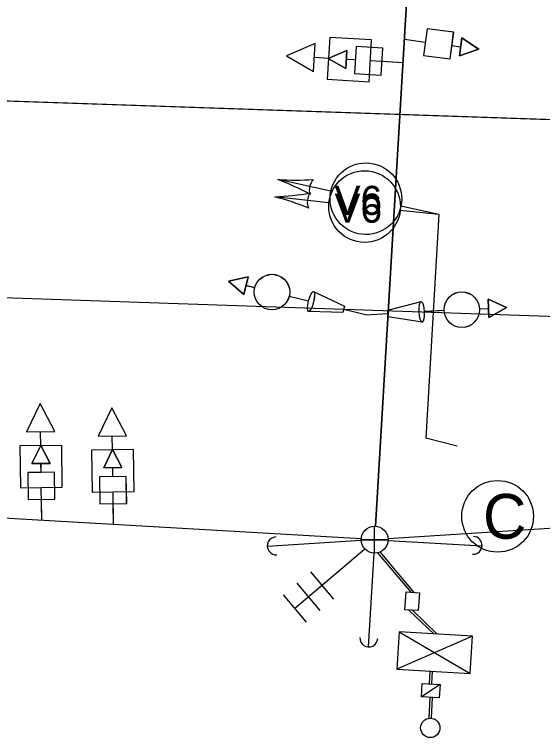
# Model space of a CAD drawing. Extents: x 647787 to 668496, y 640478 to 654412.
# Drawn here: x 661688.8 to 661747.7, y 647230.2 to 647310.9 of the extents above; entities that cross this region are included whole.
import ezdxf

# ---------------------------------------------------------------- set-up
doc = ezdxf.new("R2010")
doc.units = 0
for name, color, linetype in [('Default', 7, 'Continuous'), ('TEMP_SIGNAL POLES', 7, 'Continuous'), ('TEMP_SIGNAL_CONDUIT', 7, 'Continuous'), ('TEMP_SIGNAL_CONTROLLER', 7, 'Continuous'), ('TEMP_SIGNAL_HEAD_STAGE 2', 7, 'Continuous'), ('TEMP_SIGNAL_HEAD_STAGE 2 SHILO', 7, 'Continuous'), ('TEMP_SIGNAL_HEAD_Stage 3', 7, 'Continuous'), ('TEMP_SIGNAL_HEAD_STAGE 4 SHILO_OLD', 7, 'Continuous'), ('TEMP_SIGNAL_HEAD_STAGE4', 7, 'Continuous'), ('TEMP_SIGNAL_POLE_STAGE 2-3', 7, 'Continuous'), ('TEMP_SIGNAL_POLES_STAGE 2', 7, 'Continuous'), ('TEMP_SIGNAL_POLES_STAGES 3-4', 7, 'Continuous'), ('TEMP_SIGNAL_PULL BOX', 7, 'Continuous'), ('TEXT_TEMP_SIGNAL_POLES_STAGE 2', 7, 'Continuous'), ('TEXT_TEMP_SIGNAL_POLES_STAGE 3', 7, 'Continuous'), ('TEXT_TEMP_SIGNAL_POLES_STAGE 4', 7, 'Continuous')]:
    doc.layers.add(name, color=color, linetype=linetype)

msp = doc.modelspace()

# ---------------------------------------------------------------- linework, layer by layer
at = {"layer": 'Default'}
for points in [[(662136.439, 647331.769), (661882.019, 647294.613), (661114.402, 647320.889)], [(662108.288, 647310.771), (661853.868, 647273.614), (661086.251, 647299.89)], [(661761.55, 647298.737), (661606.212, 647304.054)], [(661761.55, 647298.737), (661606.212, 647304.054)]]:
    msp.add_lwpolyline(points, dxfattribs=at)
at = {"layer": 'TEMP_SIGNAL POLES'}
for p, q in [((661728.991, 647250.813), (661728.991, 647253.813)), ((661728.991, 647250.813), (661728.991, 647253.813)), ((661728.991, 647250.813), (661728.991, 647253.813)), ((661728.993, 647250.815), (661728.993, 647253.815)), ((661727.491, 647252.313), (661730.491, 647252.313)), ((661727.491, 647252.313), (661730.491, 647252.313)), ((661727.491, 647252.313), (661730.491, 647252.313)), ((661727.493, 647252.315), (661730.493, 647252.315)), ((661721.821, 647248.739), (661724.408, 647245.689)), ((661721.821, 647248.739), (661724.408, 647245.689)), ((661721.821, 647248.739), (661724.408, 647245.689)), ((661721.824, 647248.741), (661724.411, 647245.69)), ((661720.296, 647247.446), (661722.883, 647244.395)), ((661720.296, 647247.446), (661722.883, 647244.395)), ((661720.296, 647247.446), (661722.883, 647244.395)), ((661720.298, 647247.448), (661722.885, 647244.397)), ((661718.77, 647246.153), (661721.357, 647243.102)), ((661718.77, 647246.153), (661721.357, 647243.102)), ((661718.77, 647246.153), (661721.357, 647243.102)), ((661718.773, 647246.154), (661721.36, 647243.103))]:
    msp.add_line(p, q, dxfattribs=at)
for points in [[(661720.064, 647244.627), (661727.906, 647251.277)], [(661720.064, 647244.627), (661727.906, 647251.277)], [(661720.064, 647244.627), (661727.906, 647251.277)], [(661720.066, 647244.629), (661727.909, 647251.279)]]:
    msp.add_lwpolyline(points, dxfattribs=at)
for centre in [(661728.991, 647252.313), (661728.991, 647252.313), (661728.991, 647252.313), (661728.993, 647252.315)]:
    msp.add_circle(centre, 1.5, dxfattribs=at)
at = {"layer": 'TEMP_SIGNAL_CONDUIT'}
for p, q in [((661733.402, 647246.426), (661729.611, 647250.947)), ((661733.402, 647246.426), (661729.611, 647250.947)), ((661733.057, 647246.448), (661729.359, 647250.859)), ((661733.057, 647246.448), (661729.359, 647250.859)), ((661735.579, 647241.795), (661732.816, 647244.459)), ((661735.579, 647241.795), (661732.816, 647244.459)), ((661735.963, 647241.772), (661733.201, 647244.436)), ((661735.963, 647241.772), (661733.201, 647244.436)), ((661735.119, 647236.217), (661735.196, 647237.651)), ((661735.119, 647236.217), (661735.196, 647237.651)), ((661735.369, 647236.206), (661735.446, 647237.636)), ((661735.369, 647236.206), (661735.446, 647237.636)), ((661736.294, 647236.149), (661734.21, 647234.767)), ((661736.294, 647236.149), (661734.21, 647234.767)), ((661735.071, 647232.382), (661735.196, 647234.703)), ((661735.071, 647232.382), (661735.196, 647234.703)), ((661735.322, 647232.383), (661735.446, 647234.688)), ((661735.322, 647232.383), (661735.446, 647234.688))]:
    msp.add_line(p, q, dxfattribs=at)
msp.add_lwpolyline([(661734.297, 647236.265), (661736.294, 647236.149), (661736.207, 647234.652), (661734.21, 647234.767)], close=True, dxfattribs=at)
msp.add_lwpolyline([(661734.297, 647236.265), (661736.294, 647236.149), (661736.207, 647234.652), (661734.21, 647234.767)], close=True, dxfattribs=at)
at = {"layer": 'TEMP_SIGNAL_CONTROLLER'}
for p, q in [((661739.919, 647241.533), (661731.465, 647237.876)), ((661739.919, 647241.533), (661731.465, 647237.876)), ((661731.715, 647242.028), (661739.668, 647237.381)), ((661731.715, 647242.028), (661739.668, 647237.381))]:
    msp.add_line(p, q, dxfattribs=at)
msp.add_lwpolyline([(661739.668, 647237.381), (661739.919, 647241.533), (661731.715, 647242.028), (661731.465, 647237.876)], close=True, dxfattribs=at)
msp.add_lwpolyline([(661739.668, 647237.381), (661739.919, 647241.533), (661731.715, 647242.028), (661731.465, 647237.876)], close=True, dxfattribs=at)
msp.add_circle((661735.202, 647231.31), 1.08, dxfattribs=at)
msp.add_circle((661735.202, 647231.31), 1.08, dxfattribs=at)
at = {"layer": 'TEMP_SIGNAL_HEAD_STAGE 2'}
for p, q in [((661724.106, 647291.217), (661718.18, 647292.507)), ((661736.154, 647288.593), (661731.923, 647289.515)), ((661738.193, 647262.746), (661734.697, 647263.636))]:
    msp.add_line(p, q, dxfattribs=at)
for points in [[(661725.884, 647306.918), (661725.762, 647304.898), (661723.811, 647306.029), (661725.884, 647306.918)], [(661725.884, 647306.918), (661725.762, 647304.898), (661723.811, 647306.029), (661725.884, 647306.918)], [(661725.884, 647306.918), (661725.762, 647304.898), (661723.811, 647306.029), (661725.884, 647306.918)], [(661725.887, 647306.919), (661725.765, 647304.9), (661723.813, 647306.031), (661725.887, 647306.919)], [(661726.822, 647305.847), (661725.823, 647305.908)], [(661726.822, 647305.847), (661725.823, 647305.908)], [(661726.822, 647305.847), (661725.823, 647305.908)], [(661726.824, 647305.849), (661725.826, 647305.91)], [(661732.156, 647305.525), (661729.816, 647305.667)], [(661732.156, 647305.525), (661729.816, 647305.667)], [(661732.156, 647305.525), (661729.816, 647305.667)], [(661732.158, 647305.527), (661729.818, 647305.668)], [(661736.154, 647288.593), (661734.697, 647263.636)], [(661692.77, 647260.823), (661690.746, 647260.796), (661691.731, 647262.825), (661692.77, 647260.823)], [(661692.77, 647260.823), (661690.746, 647260.796), (661691.731, 647262.825), (661692.77, 647260.823)], [(661692.77, 647260.823), (661690.746, 647260.796), (661691.731, 647262.825), (661692.77, 647260.823)], [(661692.772, 647260.825), (661690.749, 647260.798), (661691.733, 647262.827), (661692.772, 647260.825)], [(661700.777, 647260.359), (661698.753, 647260.332), (661699.738, 647262.361), (661700.777, 647260.359)], [(661700.777, 647260.359), (661698.753, 647260.332), (661699.738, 647262.361), (661700.777, 647260.359)], [(661700.777, 647260.359), (661698.753, 647260.332), (661699.738, 647262.361), (661700.777, 647260.359)], [(661700.779, 647260.361), (661698.756, 647260.334), (661699.74, 647262.363), (661700.779, 647260.361)], [(661691.771, 647259.809), (661691.758, 647260.809)], [(661691.771, 647259.809), (661691.758, 647260.809)], [(661691.771, 647259.809), (661691.758, 647260.809)], [(661691.774, 647259.811), (661691.76, 647260.811)], [(661699.778, 647259.345), (661699.765, 647260.345)], [(661699.778, 647259.345), (661699.765, 647260.345)], [(661699.778, 647259.345), (661699.765, 647260.345)], [(661699.781, 647259.347), (661699.767, 647260.347)], [(661691.843, 647254.466), (661691.811, 647256.81)], [(661691.843, 647254.466), (661691.811, 647256.81)], [(661691.843, 647254.466), (661691.811, 647256.81)], [(661691.845, 647254.467), (661691.814, 647256.811)], [(661699.85, 647254.002), (661699.818, 647256.346)], [(661699.85, 647254.002), (661699.818, 647256.346)], [(661699.85, 647254.002), (661699.818, 647256.346)], [(661699.852, 647254.003), (661699.821, 647256.347)]]:
    msp.add_lwpolyline(points, dxfattribs=at)
for points in [[(661723.811, 647306.029), (661725.762, 647304.898), (661725.884, 647306.918)], [(661723.811, 647306.029), (661725.762, 647304.898), (661725.884, 647306.918)], [(661723.811, 647306.029), (661725.762, 647304.898), (661725.884, 647306.918)], [(661723.813, 647306.031), (661725.765, 647304.9), (661725.887, 647306.919)], [(661729.726, 647304.169), (661729.906, 647307.164), (661726.912, 647307.345), (661726.731, 647304.35)], [(661729.726, 647304.169), (661729.906, 647307.164), (661726.912, 647307.345), (661726.731, 647304.35)], [(661729.726, 647304.169), (661729.906, 647307.164), (661726.912, 647307.345), (661726.731, 647304.35)], [(661729.728, 647304.171), (661729.909, 647307.166), (661726.914, 647307.347), (661726.733, 647304.352)], [(661691.731, 647262.825), (661690.746, 647260.796), (661692.77, 647260.823)], [(661691.731, 647262.825), (661690.746, 647260.796), (661692.77, 647260.823)], [(661691.731, 647262.825), (661690.746, 647260.796), (661692.77, 647260.823)], [(661691.733, 647262.827), (661690.749, 647260.798), (661692.772, 647260.825)], [(661699.738, 647262.361), (661698.753, 647260.332), (661700.777, 647260.359)], [(661699.738, 647262.361), (661698.753, 647260.332), (661700.777, 647260.359)], [(661699.738, 647262.361), (661698.753, 647260.332), (661700.777, 647260.359)], [(661699.74, 647262.363), (661698.756, 647260.334), (661700.779, 647260.361)], [(661690.312, 647256.79), (661693.311, 647256.83), (661693.271, 647259.829), (661690.272, 647259.789)], [(661690.312, 647256.79), (661693.311, 647256.83), (661693.271, 647259.829), (661690.272, 647259.789)], [(661690.312, 647256.79), (661693.311, 647256.83), (661693.271, 647259.829), (661690.272, 647259.789)], [(661690.314, 647256.791), (661693.314, 647256.831), (661693.274, 647259.831), (661690.274, 647259.791)], [(661698.318, 647256.326), (661701.318, 647256.366), (661701.278, 647259.365), (661698.278, 647259.325)], [(661698.318, 647256.326), (661701.318, 647256.366), (661701.278, 647259.365), (661698.278, 647259.325)], [(661698.318, 647256.326), (661701.318, 647256.366), (661701.278, 647259.365), (661698.278, 647259.325)], [(661698.321, 647256.327), (661701.321, 647256.368), (661701.28, 647259.367), (661698.281, 647259.327)]]:
    msp.add_lwpolyline(points, close=True, dxfattribs=at)
msp.add_ellipse((661728.015, 647290.366), major_axis=(-3.908, 0.851), ratio=0.999282, dxfattribs=at)
for centre, major_axis, start_param, end_param in [((661720.06, 647321.899), (28.797, -6.271), 4.862825, 4.99788), ((661707.68, 647264.994), (-28.795, 6.27), 4.427266, 4.562321), ((661723.327, 647291.387), (-1.591, 0.347), 5.727345, 6.839026)]:
    msp.add_ellipse(centre, major_axis=major_axis, ratio=0.999282, start_param=start_param, end_param=end_param, dxfattribs=at)
at = {"layer": 'TEMP_SIGNAL_HEAD_STAGE 2 SHILO'}
for points in [[(661728.365, 647303.41), (661728.647, 647308.082), (661723.975, 647308.364), (661723.693, 647303.692)], [(661728.365, 647303.41), (661728.647, 647308.082), (661723.975, 647308.364), (661723.693, 647303.692)], [(661719.138, 647306.311), (661722.182, 647304.547), (661722.372, 647307.697)], [(661719.138, 647306.311), (661722.182, 647304.547), (661722.372, 647307.697)], [(661691.669, 647267.506), (661690.133, 647264.341), (661693.289, 647264.383)], [(661691.669, 647267.506), (661690.133, 647264.341), (661693.289, 647264.383)], [(661699.676, 647267.042), (661698.139, 647263.877), (661701.296, 647263.919)], [(661699.676, 647267.042), (661698.139, 647263.877), (661701.296, 647263.919)], [(661689.454, 647258.091), (661694.134, 647258.154), (661694.071, 647262.833), (661689.392, 647262.771)], [(661689.454, 647258.091), (661694.134, 647258.154), (661694.071, 647262.833), (661689.392, 647262.771)], [(661697.461, 647257.627), (661702.141, 647257.69), (661702.078, 647262.369), (661697.399, 647262.307)], [(661697.461, 647257.627), (661702.141, 647257.69), (661702.078, 647262.369), (661697.399, 647262.307)]]:
    msp.add_lwpolyline(points, close=True, dxfattribs=at)
for points in [[(661723.834, 647306.028), (661722.277, 647306.122)], [(661723.834, 647306.028), (661722.277, 647306.122)], [(661732.156, 647305.525), (661728.506, 647305.746)], [(661732.156, 647305.525), (661728.506, 647305.746)], [(661691.731, 647262.802), (661691.711, 647264.362)], [(661691.731, 647262.802), (661691.711, 647264.362)], [(661699.738, 647262.338), (661699.718, 647263.898)], [(661699.738, 647262.338), (661699.718, 647263.898)], [(661691.843, 647254.466), (661691.794, 647258.122)], [(661691.843, 647254.466), (661691.794, 647258.122)], [(661699.85, 647254.002), (661699.801, 647257.658)], [(661699.85, 647254.002), (661699.801, 647257.658)]]:
    msp.add_lwpolyline(points, dxfattribs=at)
at = {"layer": 'TEMP_SIGNAL_HEAD_Stage 3'}
for p, q in [((661723.895, 647289.92), (661717.866, 647290.572)), ((661736.154, 647288.593), (661731.849, 647289.059)), ((661738.193, 647262.746), (661734.697, 647263.636))]:
    msp.add_line(p, q, dxfattribs=at)
msp.add_lwpolyline([(661736.154, 647288.593), (661734.697, 647263.636)], dxfattribs=at)
msp.add_ellipse((661727.872, 647289.49), major_axis=(-3.977, 0.43), ratio=0.999282, dxfattribs=at)
for centre, major_axis, start_param, end_param in [((661716.608, 647319.997), (29.301, -3.171), 4.862825, 4.99788), ((661710.353, 647262.098), (-29.299, 3.171), 4.427266, 4.562321), ((661723.102, 647290.007), (-1.619, 0.175), 5.727345, 6.839026)]:
    msp.add_ellipse(centre, major_axis=major_axis, ratio=0.999282, start_param=start_param, end_param=end_param, dxfattribs=at)
at = {"layer": 'TEMP_SIGNAL_HEAD_STAGE 4 SHILO_OLD'}
for points in [[(661714.89, 647281.64), (661714.393, 647279.679), (661712.687, 647281.155), (661714.89, 647281.64)], [(661714.89, 647281.64), (661714.393, 647279.679), (661712.687, 647281.155), (661714.89, 647281.64)], [(661715.611, 647280.413), (661714.641, 647280.659)], [(661715.611, 647280.413), (661714.641, 647280.659)], [(661722.178, 647280.008), (661725.643, 647278.374)], [(661722.178, 647280.008), (661725.643, 647278.374)], [(661719.46, 647279.483), (661721.616, 647278.962)], [(661719.46, 647279.483), (661721.616, 647278.962)], [(661725.643, 647278.374), (661725.458, 647277.649)], [(661725.643, 647278.374), (661725.458, 647277.649)], [(661730.462, 647277.917), (661734.187, 647278.89)], [(661730.462, 647277.917), (661734.187, 647278.89)], [(661741.73, 647277.116), (661741.646, 647279.137), (661743.702, 647278.21), (661741.73, 647277.116)], [(661741.73, 647277.116), (661741.646, 647279.137), (661743.702, 647278.21), (661741.73, 647277.116)], [(661725.458, 647277.649), (661721.61, 647277.782)], [(661725.458, 647277.649), (661721.61, 647277.782)], [(661727.98, 647277.417), (661725.549, 647278.007)], [(661727.98, 647277.417), (661725.549, 647278.007)], [(661730.492, 647277.17), (661730.462, 647277.917)], [(661730.492, 647277.17), (661730.462, 647277.917)], [(661736.734, 647277.875), (661734.519, 647277.758)], [(661736.734, 647277.875), (661734.519, 647277.758)], [(661740.689, 647278.085), (661741.688, 647278.126)], [(661740.689, 647278.085), (661741.688, 647278.126)], [(661727.98, 647277.417), (661730.477, 647277.547)], [(661727.98, 647277.417), (661730.477, 647277.547)], [(661734.28, 647276.595), (661730.492, 647277.17)], [(661734.28, 647276.595), (661730.492, 647277.17)]]:
    msp.add_lwpolyline(points, dxfattribs=at)
for points in [[(661712.687, 647281.155), (661714.393, 647279.679), (661714.89, 647281.64)], [(661712.687, 647281.155), (661714.393, 647279.679), (661714.89, 647281.64)], [(661743.702, 647278.21), (661741.646, 647279.137), (661741.73, 647277.116)], [(661743.702, 647278.21), (661741.646, 647279.137), (661741.73, 647277.116)]]:
    msp.add_lwpolyline(points, close=True, dxfattribs=at)
for centre in [(661717.535, 647279.948), (661717.535, 647279.948), (661738.712, 647277.98), (661738.712, 647277.98)]:
    msp.add_circle(centre, 1.98, dxfattribs=at)
for centre, major_axis in [((661721.894, 647278.895), (-0.284, -1.113)), ((661721.894, 647278.895), (-0.284, -1.113)), ((661734.234, 647277.742), (-0.046, 1.147)), ((661734.234, 647277.742), (-0.046, 1.147))]:
    msp.add_ellipse(centre, major_axis=major_axis, ratio=0.249111, dxfattribs=at)
at = {"layer": 'TEMP_SIGNAL_HEAD_STAGE4'}
for p, q in [((661723.895, 647289.92), (661717.866, 647290.572)), ((661736.154, 647288.593), (661731.849, 647289.059)), ((661738.193, 647262.746), (661734.697, 647263.636))]:
    msp.add_line(p, q, dxfattribs=at)
for points in [[(661734.835, 647309.334), (661734.437, 647306.36), (661737.41, 647305.962), (661737.809, 647308.935)], [(661734.835, 647309.334), (661734.437, 647306.36), (661737.41, 647305.962), (661737.809, 647308.935)], [(661734.835, 647309.334), (661734.437, 647306.36), (661737.41, 647305.962), (661737.809, 647308.935)], [(661734.838, 647309.336), (661734.439, 647306.362), (661737.413, 647305.964), (661737.811, 647308.937)], [(661740.599, 647307.048), (661738.735, 647308.319), (661738.466, 647306.313)], [(661740.599, 647307.048), (661738.735, 647308.319), (661738.466, 647306.313)], [(661740.599, 647307.048), (661738.735, 647308.319), (661738.466, 647306.313)], [(661740.601, 647307.05), (661738.738, 647308.32), (661738.469, 647306.315)], [(661712.687, 647281.155), (661714.393, 647279.679), (661714.89, 647281.64)], [(661712.687, 647281.155), (661714.393, 647279.679), (661714.89, 647281.64)], [(661712.687, 647281.155), (661714.393, 647279.679), (661714.89, 647281.64)], [(661712.69, 647281.157), (661714.395, 647279.68), (661714.892, 647281.642)], [(661743.702, 647278.21), (661741.646, 647279.137), (661741.73, 647277.116)], [(661743.702, 647278.21), (661741.646, 647279.137), (661741.73, 647277.116)], [(661743.702, 647278.21), (661741.646, 647279.137), (661741.73, 647277.116)], [(661743.704, 647278.212), (661741.648, 647279.139), (661741.732, 647277.117)]]:
    msp.add_lwpolyline(points, close=True, dxfattribs=at)
for points in [[(661738.466, 647306.313), (661738.735, 647308.319), (661740.599, 647307.048), (661738.466, 647306.313)], [(661738.466, 647306.313), (661738.735, 647308.319), (661740.599, 647307.048), (661738.466, 647306.313)], [(661738.466, 647306.313), (661738.735, 647308.319), (661740.599, 647307.048), (661738.466, 647306.313)], [(661738.469, 647306.315), (661738.738, 647308.32), (661740.601, 647307.05), (661738.469, 647306.315)], [(661732.313, 647308.159), (661734.636, 647307.847)], [(661732.313, 647308.159), (661734.636, 647307.847)], [(661732.313, 647308.159), (661734.636, 647307.847)], [(661732.315, 647308.16), (661734.639, 647307.849)], [(661737.61, 647307.449), (661738.601, 647307.316)], [(661737.61, 647307.449), (661738.601, 647307.316)], [(661737.61, 647307.449), (661738.601, 647307.316)], [(661737.612, 647307.451), (661738.603, 647307.318)], [(661736.154, 647288.593), (661734.697, 647263.636)], [(661714.89, 647281.64), (661714.393, 647279.679), (661712.687, 647281.155), (661714.89, 647281.64)], [(661714.89, 647281.64), (661714.393, 647279.679), (661712.687, 647281.155), (661714.89, 647281.64)], [(661714.89, 647281.64), (661714.393, 647279.679), (661712.687, 647281.155), (661714.89, 647281.64)], [(661714.892, 647281.642), (661714.395, 647279.68), (661712.69, 647281.157), (661714.892, 647281.642)], [(661715.611, 647280.413), (661714.641, 647280.659)], [(661715.611, 647280.413), (661714.641, 647280.659)], [(661715.611, 647280.413), (661714.641, 647280.659)], [(661715.613, 647280.415), (661714.644, 647280.661)], [(661722.178, 647280.008), (661725.643, 647278.374)], [(661722.178, 647280.008), (661725.643, 647278.374)], [(661722.178, 647280.008), (661725.643, 647278.374)], [(661722.18, 647280.009), (661725.645, 647278.376)], [(661719.46, 647279.483), (661721.616, 647278.962)], [(661719.46, 647279.483), (661721.616, 647278.962)], [(661719.46, 647279.483), (661721.616, 647278.962)], [(661719.462, 647279.485), (661721.618, 647278.964)], [(661725.643, 647278.374), (661725.458, 647277.649)], [(661725.643, 647278.374), (661725.458, 647277.649)], [(661725.643, 647278.374), (661725.458, 647277.649)], [(661725.645, 647278.376), (661725.46, 647277.651)], [(661730.462, 647277.917), (661734.187, 647278.89)], [(661730.462, 647277.917), (661734.187, 647278.89)], [(661730.462, 647277.917), (661734.187, 647278.89)], [(661730.465, 647277.919), (661734.19, 647278.892)], [(661741.73, 647277.116), (661741.646, 647279.137), (661743.702, 647278.21), (661741.73, 647277.116)], [(661741.73, 647277.116), (661741.646, 647279.137), (661743.702, 647278.21), (661741.73, 647277.116)], [(661741.73, 647277.116), (661741.646, 647279.137), (661743.702, 647278.21), (661741.73, 647277.116)], [(661741.732, 647277.117), (661741.648, 647279.139), (661743.704, 647278.212), (661741.732, 647277.117)], [(661725.458, 647277.649), (661721.61, 647277.782)], [(661725.458, 647277.649), (661721.61, 647277.782)], [(661725.458, 647277.649), (661721.61, 647277.782)], [(661725.46, 647277.651), (661721.613, 647277.784)], [(661727.98, 647277.417), (661725.549, 647278.007)], [(661727.98, 647277.417), (661725.549, 647278.007)], [(661727.98, 647277.417), (661725.549, 647278.007)], [(661727.982, 647277.419), (661725.552, 647278.009)], [(661730.492, 647277.17), (661730.462, 647277.917)], [(661730.492, 647277.17), (661730.462, 647277.917)], [(661730.492, 647277.17), (661730.462, 647277.917)], [(661730.495, 647277.171), (661730.465, 647277.919)], [(661736.734, 647277.875), (661734.519, 647277.758)], [(661736.734, 647277.875), (661734.519, 647277.758)], [(661736.734, 647277.875), (661734.519, 647277.758)], [(661736.737, 647277.877), (661734.522, 647277.759)], [(661740.689, 647278.085), (661741.688, 647278.126)], [(661740.689, 647278.085), (661741.688, 647278.126)], [(661740.689, 647278.085), (661741.688, 647278.126)], [(661740.691, 647278.087), (661741.69, 647278.128)], [(661727.98, 647277.417), (661730.477, 647277.547)], [(661727.98, 647277.417), (661730.477, 647277.547)], [(661727.98, 647277.417), (661730.477, 647277.547)], [(661727.982, 647277.419), (661730.48, 647277.549)], [(661734.28, 647276.595), (661730.492, 647277.17)], [(661734.28, 647276.595), (661730.492, 647277.17)], [(661734.28, 647276.595), (661730.492, 647277.17)], [(661734.282, 647276.597), (661730.495, 647277.171)]]:
    msp.add_lwpolyline(points, dxfattribs=at)
for centre in [(661717.535, 647279.948), (661717.535, 647279.948), (661717.535, 647279.948), (661717.538, 647279.95), (661738.712, 647277.98), (661738.712, 647277.98), (661738.712, 647277.98), (661738.714, 647277.982)]:
    msp.add_circle(centre, 1.98, dxfattribs=at)
for centre, major_axis, ratio in [((661727.872, 647289.49), (-3.977, 0.43), 0.999282), ((661721.894, 647278.895), (-0.284, -1.113), 0.249111), ((661721.894, 647278.895), (-0.284, -1.113), 0.249111), ((661721.894, 647278.895), (-0.284, -1.113), 0.249111), ((661721.896, 647278.897), (-0.284, -1.113), 0.249111), ((661734.234, 647277.742), (-0.046, 1.147), 0.249111), ((661734.234, 647277.742), (-0.046, 1.147), 0.249111), ((661734.234, 647277.742), (-0.046, 1.147), 0.249111), ((661734.236, 647277.744), (-0.046, 1.147), 0.249111)]:
    msp.add_ellipse(centre, major_axis=major_axis, ratio=ratio, dxfattribs=at)
for centre, major_axis, start_param, end_param in [((661716.608, 647319.997), (29.301, -3.171), 4.862825, 4.99788), ((661710.353, 647262.098), (-29.299, 3.171), 4.427266, 4.562321), ((661723.102, 647290.007), (-1.619, 0.175), 5.727345, 6.839026)]:
    msp.add_ellipse(centre, major_axis=major_axis, ratio=0.999282, start_param=start_param, end_param=end_param, dxfattribs=at)
at = {"layer": 'TEMP_SIGNAL_POLE_STAGE 2-3'}
msp.add_line((661727.493, 647252.4), (661613.044, 647259.031), dxfattribs=at)
msp.add_line((661727.493, 647252.4), (661613.044, 647259.031), dxfattribs=at)
at = {"layer": 'TEMP_SIGNAL_POLES_STAGE 2'}
for p, q in [((661737.273, 647391.538), (661729.08, 647253.81)), ((661737.273, 647391.538), (661729.08, 647253.81)), ((661737.273, 647391.538), (661729.08, 647253.81)), ((661737.275, 647391.54), (661729.082, 647253.812)), ((661730.488, 647252.226), (661740.971, 647251.619)), ((661730.488, 647252.226), (661740.971, 647251.619)), ((661730.488, 647252.226), (661740.971, 647251.619)), ((661730.491, 647252.228), (661740.973, 647251.621)), ((661728.902, 647250.816), (661728.278, 647240.334)), ((661728.902, 647250.816), (661728.278, 647240.334)), ((661728.902, 647250.816), (661728.278, 647240.334)), ((661728.904, 647250.818), (661728.281, 647240.336))]:
    msp.add_line(p, q, dxfattribs=at)
for centre, start, end in [((661739.972, 647251.677), 266.68389, 86.68389), ((661739.972, 647251.677), 266.68389, 86.68389), ((661739.972, 647251.677), 266.68389, 86.68389), ((661739.975, 647251.679), 266.68389, 86.68389), ((661728.338, 647241.333), 176.59578, 356.59578), ((661728.338, 647241.333), 176.59578, 356.59578), ((661728.338, 647241.333), 176.59578, 356.59578), ((661728.34, 647241.334), 176.59578, 356.59578)]:
    msp.add_arc(centre, 1, start, end, dxfattribs=at)
at = {"layer": 'TEMP_SIGNAL_POLES_STAGES 3-4'}
for p, q in [((661729.08, 647253.81), (661737.273, 647391.538)), ((661729.08, 647253.81), (661737.273, 647391.538)), ((661857.996, 647260.481), (661730.488, 647252.408)), ((661857.996, 647260.481), (661730.488, 647252.408)), ((661727.494, 647252.218), (661717.015, 647251.555)), ((661727.494, 647252.218), (661717.015, 647251.555)), ((661728.902, 647250.816), (661728.278, 647240.334)), ((661728.902, 647250.816), (661728.278, 647240.334))]:
    msp.add_line(p, q, dxfattribs=at)
for centre, start, end in [((661718.013, 647251.618), 93.62274, 273.62274), ((661718.013, 647251.618), 93.62274, 273.62274), ((661728.338, 647241.333), 176.59578, 356.59578), ((661728.338, 647241.333), 176.59578, 356.59578)]:
    msp.add_arc(centre, 1, start, end, dxfattribs=at)
at = {"layer": 'TEMP_SIGNAL_PULL BOX'}
msp.add_lwpolyline([(661732.366, 647244.488), (661732.493, 647246.484), (661733.99, 647246.388), (661733.863, 647244.392)], close=True, dxfattribs=at)
msp.add_lwpolyline([(661732.366, 647244.488), (661732.493, 647246.484), (661733.99, 647246.388), (661733.863, 647244.392)], close=True, dxfattribs=at)
at = {"layer": 'TEXT_TEMP_SIGNAL_POLES_STAGE 2'}
msp.add_circle((661742.716, 647254.918), 4, dxfattribs=at)
at = {"layer": 'TEXT_TEMP_SIGNAL_POLES_STAGE 3'}
msp.add_circle((661742.716, 647254.918), 4, dxfattribs=at)
at = {"layer": 'TEXT_TEMP_SIGNAL_POLES_STAGE 4'}
msp.add_circle((661742.716, 647254.918), 4, dxfattribs=at)

# ---------------------------------------------------------------- texts
at = {"layer": 'TEXT_TEMP_SIGNAL_POLES_STAGE 2'}
for s, height, p in [('V6', 3.25, (661724.512, 647288.553)), ('C', 5, (661741.083, 647252.418))]:
    msp.add_text(s, height=height, dxfattribs=at).set_placement(p)
at = {"layer": 'TEXT_TEMP_SIGNAL_POLES_STAGE 3'}
for s, height, p in [('V6', 3.25, (661724.512, 647287.69)), ('C', 5, (661741.083, 647252.418))]:
    msp.add_text(s, height=height, dxfattribs=at).set_placement(p)
at = {"layer": 'TEXT_TEMP_SIGNAL_POLES_STAGE 4'}
for s, height, p in [('V6', 3.25, (661724.512, 647287.69)), ('C', 5, (661741.083, 647252.418))]:
    msp.add_text(s, height=height, dxfattribs=at).set_placement(p)

doc.saveas('drawing.dxf')
